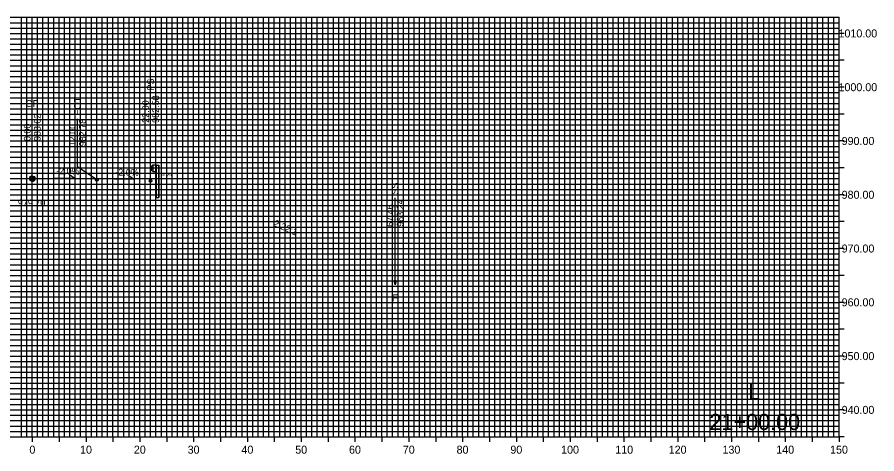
# Model space of a CAD drawing. Extents: x -157 to 157, y 932 to 1013.
# Drawn here: x -2.8 to 157, y 931.8 to 1013 of the extents above; entities that cross this region are included whole.
import ezdxf

# ---------------------------------------------------------------- set-up
doc = ezdxf.new("R2010")
doc.units = 0
for name, color, linetype in [('E_NCDOT_Terrain_Model_Boundary', 7, 'Continuous'), ('E_NCDOT_Terrain_Model_Breakline', 7, 'Continuous'), ('E_NCDOT_Terrain_Model_Contour_Imported', 7, 'Continuous'), ('E_NCDOT_Terrain_Model_Contour_Major', 7, 'Continuous'), ('E_NCDOT_Terrain_Model_Contour_Minor', 7, 'Continuous'), ('E_NCDOT_Terrain_Model_Hole', 7, 'Continuous'), ('E_NCDOT_Terrain_Model_Island', 7, 'Continuous'), ('E_NCDOT_Terrain_Model_Points_High', 7, 'Continuous'), ('E_NCDOT_Terrain_Model_Points_Low', 7, 'Continuous'), ('E_NCDOT_Terrain_Model_Triangles', 7, 'Continuous'), ('E_NCDOT_Terrain_Model_Void', 7, 'Continuous'), ('E_NCDOT_Vertical_Profile_Ground_Line', 7, 'Continuous'), ('P_HYD_Contour_Major', 7, 'Continuous'), ('P_HYD_Contour_Minor', 7, 'Continuous'), ('P_HYD_TC_Ditch_UCE', 7, 'Continuous'), ('P_HYD_TC_Surface_Grass', 7, 'Continuous'), ('P_HYD_TL_Ditch_Boundary', 7, 'Continuous')]:
    doc.layers.add(name, color=color, linetype=linetype)

msp = doc.modelspace()

# ---------------------------------------------------------------- linework, layer by layer
at = {"layer": 'E_NCDOT_Terrain_Model_Boundary'}
for p, q in [((-0.5, 983.02), (0.5, 983.02)), ((0, 983.52), (0, 982.52))]:
    msp.add_line(p, q, dxfattribs=at)
for points in [[(-0.5, 983.02), (0, 983.02), (0, 983.52)], [(0.5, 983.02), (0, 983.02), (0, 982.52)]]:
    msp.add_lwpolyline(points, dxfattribs=at)
msp.add_circle((0, 983.02), 0.5, dxfattribs=at)
for start, end in [(90, 180), (270, 0)]:
    msp.add_arc((0, 983.02), 0.5, start, end, dxfattribs=at)
at = {"layer": 'E_NCDOT_Terrain_Model_Breakline'}
for p, q in [((-150, 1013), (150, 1013)), ((-150, 1012), (150, 1012)), ((-2, 935), (-2, 1013.02)), ((-1, 935), (-1, 1013.02)), ((1, 935), (1, 1013.02)), ((2, 935), (2, 1013.02)), ((3, 935), (3, 1013.02)), ((4, 935), (4, 1013.02)), ((6, 935), (6, 1013.02)), ((7, 935), (7, 1013.02)), ((8, 935), (8, 1013.02)), ((9, 935), (9, 1013.02)), ((11, 935), (11, 1013.02)), ((12, 935), (12, 1013.02)), ((13, 935), (13, 1013.02)), ((14, 935), (14, 1013.02)), ((16, 935), (16, 1013.02)), ((17, 935), (17, 1013.02)), ((18, 935), (18, 1013.02)), ((19, 935), (19, 1013.02)), ((21, 935), (21, 1013.02)), ((22, 935), (22, 1013.02)), ((23, 935), (23, 1013.02)), ((24, 935), (24, 1013.02)), ((26, 935), (26, 1013.02)), ((27, 935), (27, 1013.02)), ((28, 935), (28, 1013.02)), ((29, 935), (29, 1013.02)), ((31, 935), (31, 1013.02)), ((32, 935), (32, 1013.02)), ((33, 935), (33, 1013.02)), ((34, 935), (34, 1013.02)), ((36, 935), (36, 1013.02)), ((37, 935), (37, 1013.02)), ((38, 935), (38, 1013.02)), ((39, 935), (39, 1013.02)), ((41, 935), (41, 1013.02)), ((42, 935), (42, 1013.02)), ((43, 935), (43, 1013.02)), ((44, 935), (44, 1013.02)), ((46, 935), (46, 1013.02)), ((47, 935), (47, 1013.02)), ((48, 935), (48, 1013.02)), ((49, 935), (49, 1013.02)), ((51, 935), (51, 1013.02)), ((52, 935), (52, 1013.02)), ((53, 935), (53, 1013.02)), ((54, 935), (54, 1013.02)), ((56, 935), (56, 1013.02)), ((57, 935), (57, 1013.02)), ((58, 935), (58, 1013.02)), ((59, 935), (59, 1013.02)), ((61, 935), (61, 1013.02)), ((62, 935), (62, 1013.02)), ((63, 935), (63, 1013.02)), ((64, 935), (64, 1013.02)), ((66, 935), (66, 1013.02)), ((67, 935), (67, 1013.02)), ((68, 935), (68, 1013.02)), ((69, 935), (69, 1013.02)), ((71, 935), (71, 1013.02)), ((72, 935), (72, 1013.02)), ((73, 935), (73, 1013.02)), ((74, 935), (74, 1013.02)), ((76, 935), (76, 1013.02)), ((77, 935), (77, 1013.02)), ((78, 935), (78, 1013.02)), ((79, 935), (79, 1013.02)), ((81, 935), (81, 1013.02)), ((82, 935), (82, 1013.02)), ((83, 935), (83, 1013.02)), ((84, 935), (84, 1013.02)), ((86, 935), (86, 1013.02)), ((87, 935), (87, 1013.02)), ((88, 935), (88, 1013.02)), ((89, 935), (89, 1013.02)), ((91, 935), (91, 1013.02)), ((92, 935), (92, 1013.02)), ((93, 935), (93, 1013.02)), ((94, 935), (94, 1013.02)), ((96, 935), (96, 1013.02)), ((97, 935), (97, 1013.02)), ((98, 935), (98, 1013.02)), ((99, 935), (99, 1013.02)), ((101, 935), (101, 1013.02)), ((102, 935), (102, 1013.02)), ((103, 935), (103, 1013.02)), ((104, 935), (104, 1013.02)), ((106, 935), (106, 1013.02)), ((107, 935), (107, 1013.02)), ((108, 935), (108, 1013.02)), ((109, 935), (109, 1013.02)), ((111, 935), (111, 1013.02)), ((112, 935), (112, 1013.02)), ((113, 935), (113, 1013.02)), ((114, 935), (114, 1013.02)), ((116, 935), (116, 1013.02)), ((117, 935), (117, 1013.02)), ((118, 935), (118, 1013.02)), ((119, 935), (119, 1013.02)), ((121, 935), (121, 1013.02)), ((122, 935), (122, 1013.02)), ((123, 935), (123, 1013.02)), ((124, 935), (124, 1013.02)), ((126, 935), (126, 1013.02)), ((127, 935), (127, 1013.02)), ((128, 935), (128, 1013.02)), ((129, 935), (129, 1013.02)), ((131, 935), (131, 1013.02)), ((132, 935), (132, 1013.02)), ((133, 935), (133, 1013.02)), ((134, 935), (134, 1013.02)), ((136, 935), (136, 1013.02)), ((137, 935), (137, 1013.02)), ((138, 935), (138, 1013.02)), ((139, 935), (139, 1013.02)), ((141, 935), (141, 1013.02)), ((142, 935), (142, 1013.02)), ((143, 935), (143, 1013.02)), ((144, 935), (144, 1013.02)), ((146, 935), (146, 1013.02)), ((147, 935), (147, 1013.02)), ((148, 935), (148, 1013.02)), ((149, 935), (149, 1013.02)), ((-150, 1011), (150, 1011)), ((-150, 1009), (150, 1009)), ((-150, 1008), (150, 1008)), ((-150, 1007), (150, 1007)), ((-150, 1006), (150, 1006)), ((-150, 1004), (150, 1004)), ((-150, 1003), (150, 1003)), ((-150, 1002), (150, 1002)), ((-150, 1001), (150, 1001)), ((-150, 999), (150, 999)), ((-150, 998), (150, 998)), ((-150, 997), (150, 997)), ((-150, 996), (150, 996)), ((-150, 994), (150, 994)), ((-150, 993), (150, 993)), ((-150, 992), (150, 992)), ((-150, 991), (150, 991)), ((-150, 989), (150, 989)), ((-150, 988), (150, 988)), ((-150, 987), (150, 987)), ((-150, 986), (150, 986)), ((-150, 984), (150, 984)), ((-150, 983), (150, 983)), ((-150, 982), (150, 982)), ((-150, 981), (150, 981)), ((-150, 979), (150, 979)), ((-150, 978), (150, 978)), ((-150, 977), (150, 977)), ((-150, 976), (150, 976)), ((-150, 974), (150, 974)), ((-150, 973), (150, 973)), ((-150, 972), (150, 972)), ((-150, 971), (150, 971)), ((-150, 969), (150, 969)), ((-150, 968), (150, 968)), ((-150, 967), (150, 967)), ((-150, 966), (150, 966)), ((-150, 964), (150, 964)), ((-150, 963), (150, 963)), ((-150, 962), (150, 962)), ((-150, 961), (150, 961)), ((-150, 959), (150, 959)), ((-150, 958), (150, 958)), ((-150, 957), (150, 957)), ((-150, 956), (150, 956)), ((-150, 954), (150, 954)), ((-150, 953), (150, 953)), ((-150, 952), (150, 952)), ((-150, 951), (150, 951)), ((-150, 949), (150, 949)), ((-150, 948), (150, 948)), ((-150, 947), (150, 947)), ((-150, 946), (150, 946)), ((-150, 944), (150, 944)), ((-150, 943), (150, 943)), ((-150, 942), (150, 942)), ((-150, 941), (150, 941)), ((-150, 939), (150, 939)), ((-150, 938), (150, 938)), ((-150, 937), (150, 937)), ((-150, 936), (150, 936))]:
    msp.add_line(p, q, dxfattribs=at)
at = {"layer": 'E_NCDOT_Terrain_Model_Contour_Imported'}
for p, q in [((4.2, 983.18), (7.8, 983.1)), ((7.8, 983.1), (7.12, 983.6)), ((15.2, 982.96), (18.8, 982.88)), ((18.8, 982.88), (18.12, 983.38))]:
    msp.add_line(p, q, dxfattribs=at)
at = {"layer": 'E_NCDOT_Terrain_Model_Contour_Minor'}
for p, q in [((8.44, 985.17), (8.44, 994.13)), ((12, 982.78), (8.44, 985.17))]:
    msp.add_line(p, q, dxfattribs=at)
at = {"layer": 'E_NCDOT_Terrain_Model_Hole'}
for p, q in [((0, 935), (0, 1013.02)), ((10, 935), (10, 1013.02)), ((20, 935), (20, 1013.02)), ((30, 935), (30, 1013.02)), ((40, 935), (40, 1013.02)), ((50, 935), (50, 1013.02)), ((60, 935), (60, 1013.02)), ((70, 935), (70, 1013.02)), ((80, 935), (80, 1013.02)), ((90, 935), (90, 1013.02)), ((100, 935), (100, 1013.02)), ((110, 935), (110, 1013.02)), ((120, 935), (120, 1013.02)), ((130, 935), (130, 1013.02)), ((140, 935), (140, 1013.02)), ((-150, 1010), (150, 1010)), ((-150, 1000), (150, 1000)), ((-150, 990), (150, 990)), ((-150, 980), (150, 980)), ((-150, 970), (150, 970)), ((-150, 960), (150, 960)), ((-150, 950), (150, 950)), ((-150, 940), (150, 940))]:
    msp.add_line(p, q, dxfattribs=at)
at = {"layer": 'E_NCDOT_Terrain_Model_Points_High'}
for p, q in [((0, 935), (0, 1013.02)), ((5, 935), (5, 1013.02)), ((10, 935), (10, 1013.02)), ((15, 935), (15, 1013.02)), ((20, 935), (20, 1013.02)), ((25, 935), (25, 1013.02)), ((30, 935), (30, 1013.02)), ((35, 935), (35, 1013.02)), ((40, 935), (40, 1013.02)), ((45, 935), (45, 1013.02)), ((50, 935), (50, 1013.02)), ((55, 935), (55, 1013.02)), ((60, 935), (60, 1013.02)), ((65, 935), (65, 1013.02)), ((70, 935), (70, 1013.02)), ((75, 935), (75, 1013.02)), ((80, 935), (80, 1013.02)), ((85, 935), (85, 1013.02)), ((90, 935), (90, 1013.02)), ((95, 935), (95, 1013.02)), ((100, 935), (100, 1013.02)), ((105, 935), (105, 1013.02)), ((110, 935), (110, 1013.02)), ((115, 935), (115, 1013.02)), ((120, 935), (120, 1013.02)), ((125, 935), (125, 1013.02)), ((130, 935), (130, 1013.02)), ((135, 935), (135, 1013.02)), ((140, 935), (140, 1013.02)), ((145, 935), (145, 1013.02)), ((-150, 1010), (150, 1010)), ((150.96, 1010), (150, 1010)), ((-150, 1005), (150, 1005)), ((150.96, 1005), (150, 1005)), ((-150, 1000), (150, 1000)), ((150.96, 1000), (150, 1000)), ((-150, 995), (150, 995)), ((150.96, 995), (150, 995)), ((-150, 990), (150, 990)), ((150.96, 990), (150, 990)), ((-150, 985), (150, 985)), ((150.96, 985), (150, 985)), ((-150, 980), (150, 980)), ((150.96, 980), (150, 980)), ((-150, 975), (150, 975)), ((150.96, 975), (150, 975)), ((-150, 970), (150, 970)), ((150.96, 970), (150, 970)), ((-150, 965), (150, 965)), ((150.96, 965), (150, 965)), ((-150, 960), (150, 960)), ((150.96, 960), (150, 960)), ((-150, 955), (150, 955)), ((150.96, 955), (150, 955)), ((-150, 950), (150, 950)), ((150.96, 950), (150, 950)), ((-150, 945), (150, 945)), ((150.96, 945), (150, 945)), ((-150, 940), (150, 940)), ((150.96, 940), (150, 940)), ((0, 935), (0, 934.04)), ((5, 935), (5, 934.04)), ((10, 935), (10, 934.04)), ((15, 935), (15, 934.04)), ((20, 935), (20, 934.04)), ((25, 935), (25, 934.04)), ((30, 935), (30, 934.04)), ((35, 935), (35, 934.04)), ((40, 935), (40, 934.04)), ((45, 935), (45, 934.04)), ((50, 935), (50, 934.04)), ((55, 935), (55, 934.04)), ((60, 935), (60, 934.04)), ((65, 935), (65, 934.04)), ((70, 935), (70, 934.04)), ((75, 935), (75, 934.04)), ((80, 935), (80, 934.04)), ((85, 935), (85, 934.04)), ((90, 935), (90, 934.04)), ((95, 935), (95, 934.04)), ((100, 935), (100, 934.04)), ((105, 935), (105, 934.04)), ((110, 935), (110, 934.04)), ((115, 935), (115, 934.04)), ((120, 935), (120, 934.04)), ((125, 935), (125, 934.04)), ((130, 935), (130, 934.04)), ((135, 935), (135, 934.04)), ((140, 935), (140, 934.04)), ((145, 935), (145, 934.04)), ((150, 935), (150, 934.04)), ((150.96, 935), (150, 935))]:
    msp.add_line(p, q, dxfattribs=at)
at = {"layer": 'E_NCDOT_Terrain_Model_Points_Low'}
for p, q in [((-150, 1013.02), (150, 1013.02)), ((150, 935), (150, 1013.02)), ((-150, 935), (150, 935))]:
    msp.add_line(p, q, dxfattribs=at)
at = {"layer": 'E_NCDOT_Vertical_Profile_Ground_Line'}
for p, q in [((22, 982.58), (22, 998.18)), ((0, 983.02), (0, 995.5)), ((67.46, 963.24), (67.46, 979.44))]:
    msp.add_line(p, q, dxfattribs=at)
for points in [[(0.3, 982.72), (-0.3, 982.72), (-0.3, 983.32), (0.3, 983.32)], [(67.46, 963.24), (67.28, 964.06), (67.63, 964.06)]]:
    msp.add_lwpolyline(points, close=True, dxfattribs=at)
for centre in [(12, 982.78), (22, 982.58)]:
    msp.add_circle(centre, 0.24, dxfattribs=at)
at = {"layer": 'P_HYD_TC_Surface_Grass'}
for p, q in [((22.29, 985.41), (22.15, 985.32)), ((22.15, 985.19), (22.36, 985.04)), ((22.36, 984.82), (22.15, 984.67)), ((22.15, 984.54), (22.29, 984.45)), ((22.39, 985.43), (22.3, 985.42)), ((22.3, 984.44), (22.39, 984.43)), ((23.06, 985.51), (22.39, 985.51)), ((22.39, 985.51), (22.39, 984.35)), ((22.39, 984.98), (22.39, 984.93)), ((22.39, 984.93), (22.39, 984.88)), ((23.06, 985.51), (23.56, 985.51)), ((23.08, 985.51), (23.06, 985.51)), ((23.06, 985.51), (23.06, 979.51)), ((23.08, 979.51), (23.08, 985.51)), ((23.56, 985.51), (23.54, 985.51)), ((23.54, 985.51), (23.54, 979.51)), ((23.56, 979.51), (23.56, 985.51)), ((22.39, 984.35), (23.06, 984.35)), ((23.06, 979.51), (23.56, 979.51)), ((23.06, 979.51), (23.08, 979.51)), ((23.54, 979.51), (23.56, 979.51))]:
    msp.add_line(p, q, dxfattribs=at)
for centre, radius, start, end in [((22.2, 985.25), 0.0787, 125.2976, 235.3478), ((22.2, 984.61), 0.0787, 124.6522, 234.7024), ((22.31, 985.39), 0.0328, 100, 125.2976), ((22.31, 984.47), 0.0328, 234.7024, 260), ((22.31, 984.98), 0.0787, 0.02, 55.3478), ((22.31, 984.88), 0.0787, 304.6522, 359.98)]:
    msp.add_arc(centre, radius, start, end, dxfattribs=at)

# ---------------------------------------------------------------- texts
at = {"layer": 'E_NCDOT_Terrain_Model_Contour_Major'}
for s, p in [('SS', (68.08, 980.04)), ('67.46', (67.14, 974.04)), ('963.24', (69.02, 974.04))]:
    msp.add_text(s, height=1.248, rotation=90, dxfattribs=at).set_placement(p)
msp.add_text('F', height=1.25, dxfattribs=at).set_placement((66.98, 960.21))
at = {"layer": 'E_NCDOT_Terrain_Model_Island'}
for s, height, p in [('1010.00', 1.488, (149.89, 1009.26)), ('1000.00', 1.488, (149.89, 999.26)), ('990.00', 1.488, (150.47, 989.26)), ('980.00', 1.488, (150.47, 979.26)), ('970.00', 1.488, (150.47, 969.26)), ('960.00', 1.488, (150.47, 959.26)), ('950.00', 1.488, (150.47, 949.26)), ('940.00', 1.488, (150.47, 939.26)), ('0', 1.49, (-0.53, 931.86)), ('10', 1.488, (8.89, 931.86)), ('20', 1.488, (18.89, 931.86)), ('30', 1.488, (28.89, 931.86)), ('40', 1.488, (38.89, 931.86)), ('50', 1.488, (48.89, 931.86)), ('60', 1.488, (58.89, 931.86)), ('70', 1.488, (68.89, 931.86)), ('80', 1.488, (78.89, 931.86)), ('90', 1.488, (88.89, 931.86)), ('100', 1.488, (98.32, 931.86)), ('110', 1.488, (108.39, 931.86)), ('120', 1.488, (118.32, 931.86)), ('130', 1.488, (128.32, 931.86)), ('140', 1.488, (138.32, 931.86)), ('150', 1.488, (148.32, 931.86))]:
    msp.add_text(s, height=height, dxfattribs=at).set_placement(p)
at = {"layer": 'E_NCDOT_Terrain_Model_Triangles'}
for s, p in [('PS', (22.62, 999.38)), ('EOT', (9.02, 994.78)), ('22.00', (21.69, 993.38)), ('982.58', (23.56, 993.38)), ('982.78', (9.96, 989.02)), ('12.00', (8.09, 989.02))]:
    msp.add_text(s, height=1.248, rotation=90, dxfattribs=at).set_placement(p)
at = {"layer": 'E_NCDOT_Terrain_Model_Void'}
msp.add_text('979.70', height=1.248, dxfattribs=at).set_placement((-2.67, 977.87))
at = {"layer": 'P_HYD_Contour_Major'}
msp.add_text('-2.0%', height=1.248, rotation=358.8542, dxfattribs=at).set_placement((4.43, 983.82))
at = {"layer": 'P_HYD_Contour_Minor'}
for s, height, rotation, p in [('-2.0%', 1.248, 358.8542, (15.43, 983.6)), ('-8.0%', 0.624, 355.4261, (23.82, 983.54)), ('2.22:1', 1.248, 335.7723, (44.75, 974.28))]:
    msp.add_text(s, height=height, rotation=rotation, dxfattribs=at).set_placement(p)
at = {"layer": 'P_HYD_TC_Ditch_UCE'}
for s, p in [('L', (133.08, 941.9)), ('21+00.00', (125.9, 936.26))]:
    msp.add_text(s, height=3, dxfattribs=at).set_placement(p)
at = {"layer": 'P_HYD_TL_Ditch_Boundary'}
msp.add_text('GP', height=1.248, dxfattribs=at).set_placement((-1.22, 996.35))
for s, p in [('983.02', (1.56, 989.98)), ('0.00', (-0.31, 989.98))]:
    msp.add_text(s, height=1.248, rotation=90, dxfattribs=at).set_placement(p)

doc.saveas('drawing.dxf')
